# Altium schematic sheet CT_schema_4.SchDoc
size 298 x 159 mm
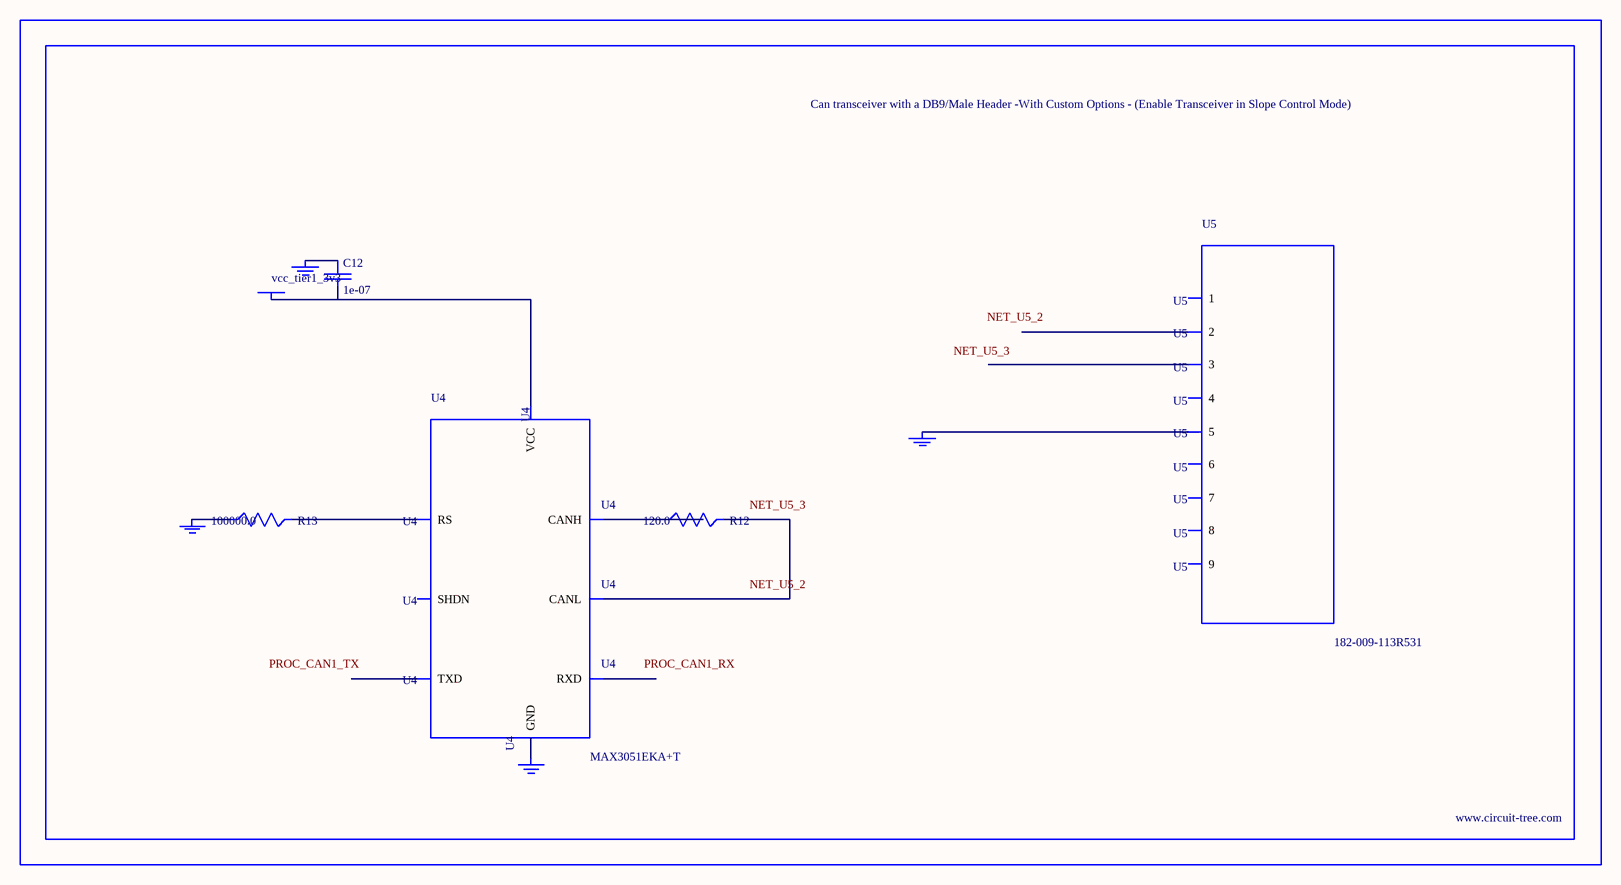
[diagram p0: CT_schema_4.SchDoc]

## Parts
BORDER3  (no value)
C12  1e-07  [C0402]
GND_INSTANCE_3_0  (no value)
GND_INSTANCE_3_1  (no value)
GND_INSTANCE_3_2  (no value)
GND_INSTANCE_3_3  (no value)
POWER_INSTANCE_3_0  vcc_tier1_3v3
R12  120.0  [R0603]
R13  100000.0  [R0603]
U4  MAX3051EKA+T  [SOT-23-8]
U5  182-009-113R531  [182-009-MALE]

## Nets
NetC12_1: C12.1 GND_INSTANCE_3_0.0(GND)
NetC12_2: C12.2 POWER_INSTANCE_3_0.0(PWR) U4.3(VCC)
NetGND_INSTANCE_3_1_0: GND_INSTANCE_3_1.0(GND) R13.1
NetGND_INSTANCE_3_2_0: GND_INSTANCE_3_2.0(GND) U4.2(GND)
NetGND_INSTANCE_3_3_0: GND_INSTANCE_3_3.0(GND) U5.5
NetR12_1: R12.1 U4.7(CANH)
NetR12_2: R12.2 U4.6(CANL)
NetR13_2: R13.2 U4.8(RS)

Not connected (* = marked no-connect by the designer): U4 1(TXD) 4(RXD) 5(SHDN); U5 1 2 3 4 6 7 8 9

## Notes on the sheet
- Labels drawn without touching a wire or pin: NET_U5_2, NET_U5_3, PROC_CAN1_RX, PROC_CAN1_TX

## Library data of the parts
BORDER3 = BORDER_PAGE3
C12 = C0402C104K3RACTU
GND_INSTANCE_3_0-GND_INSTANCE_3_3 = GND
POWER_INSTANCE_3_0 = PWR
R12 = RC0603JR-07120RL
R13 = RC0603JR-07100KL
